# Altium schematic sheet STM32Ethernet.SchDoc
size A2
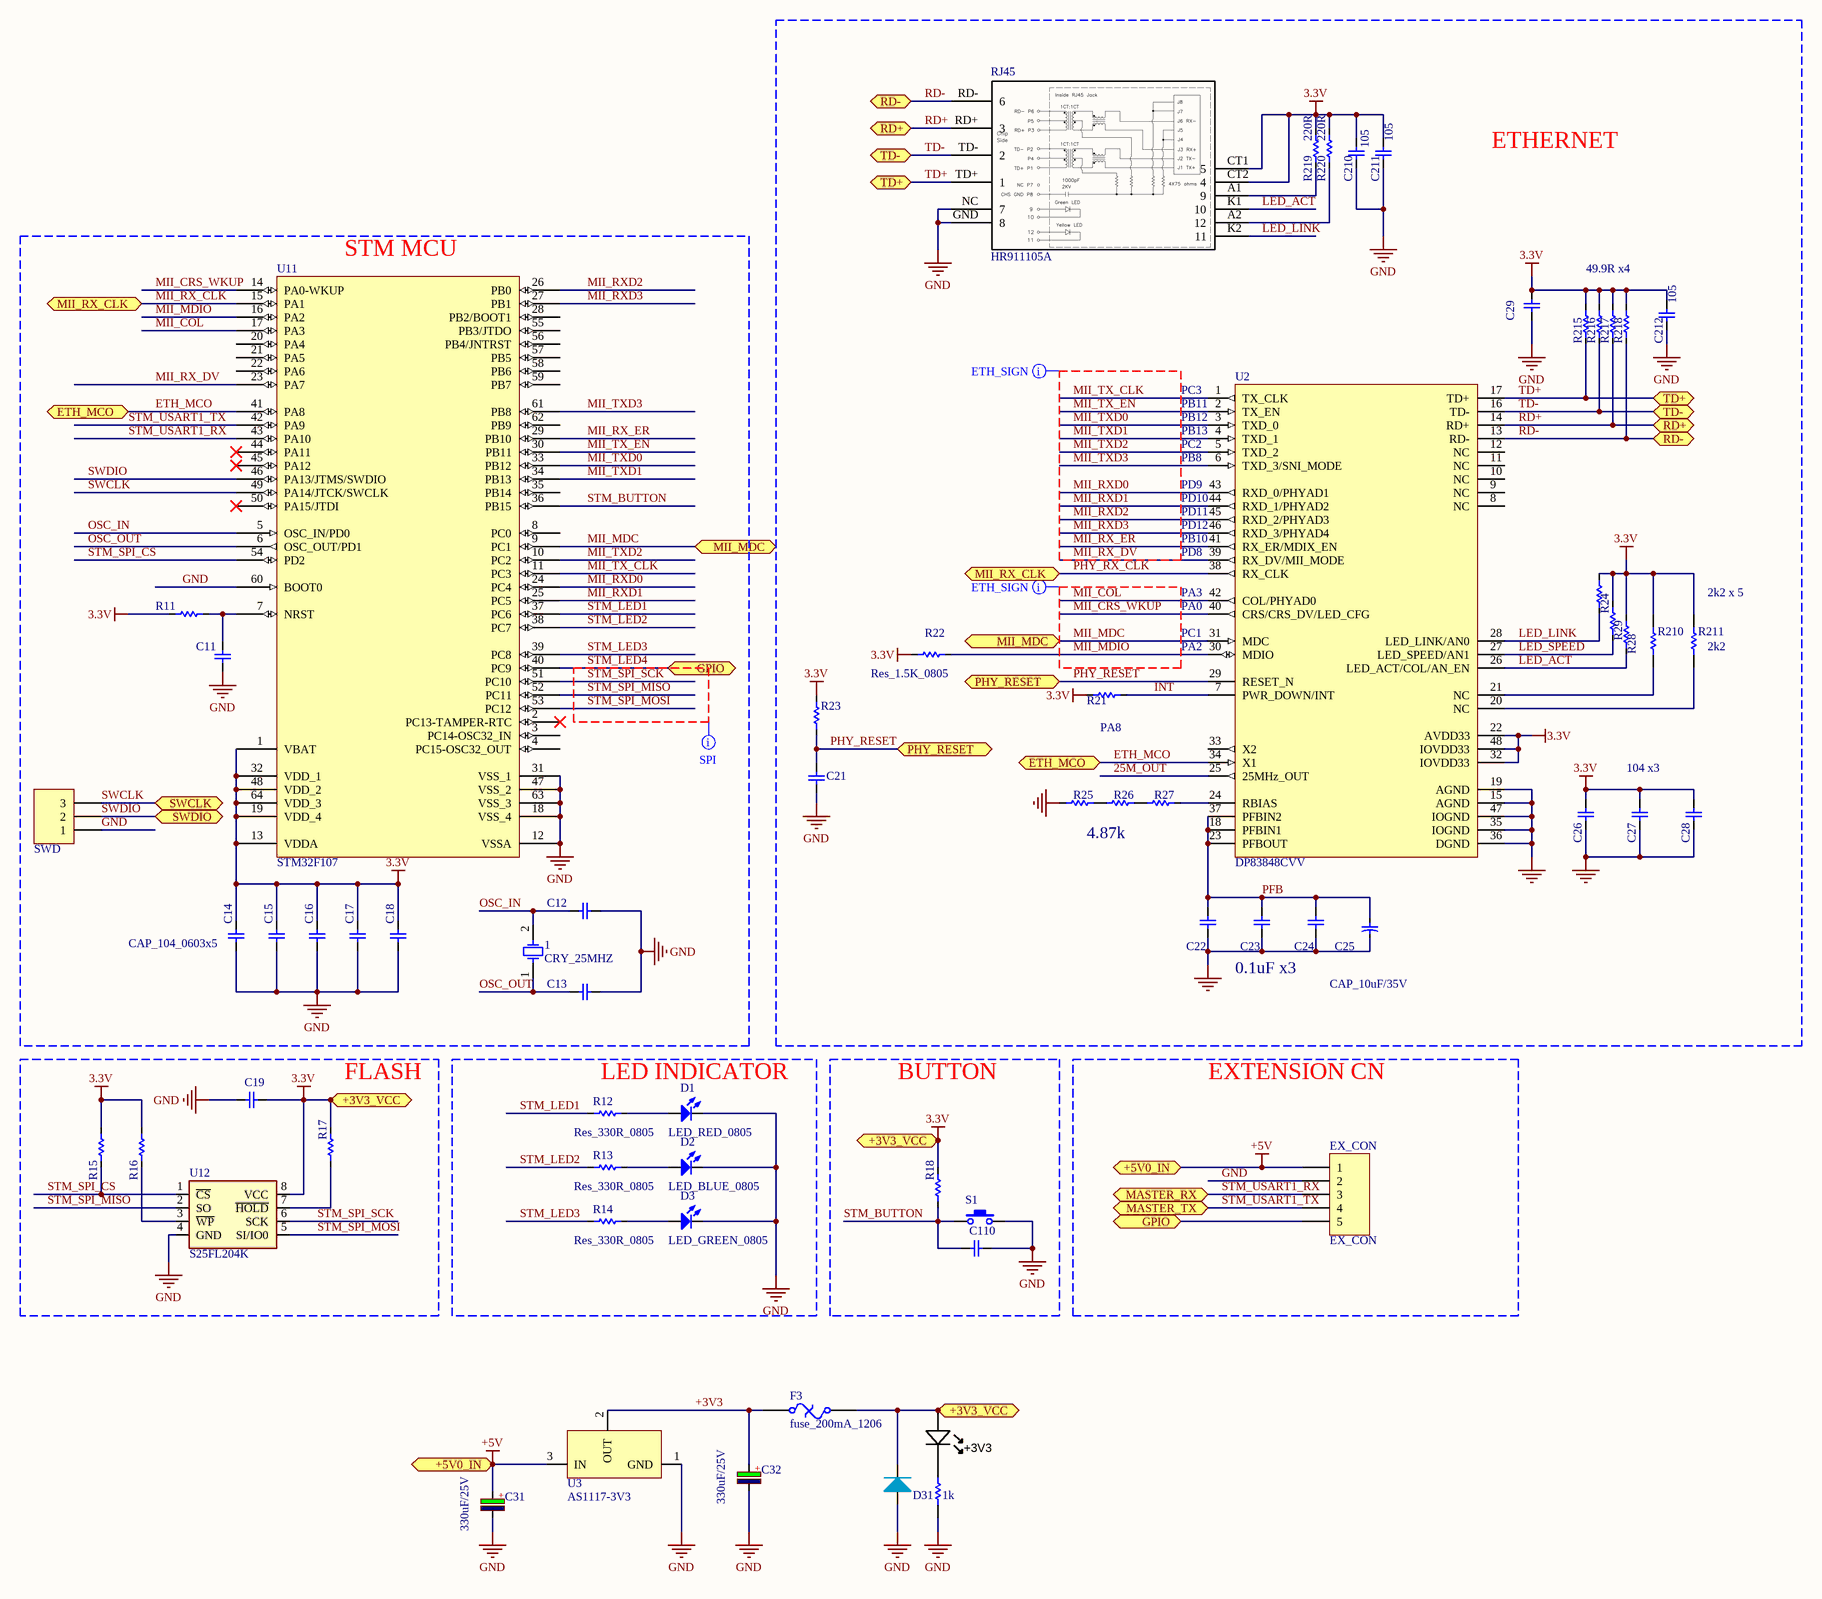
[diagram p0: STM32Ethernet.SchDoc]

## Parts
1  CRY_25MHZ  [cry]
+3V3  Blue  [LED-0805-K]  (value not drawn)
C11  CAP_102_0603  [CAP_0805_TOP]  (value not drawn)
C12  CAP_18pF_0603  [CAP_0603_TOP]  (value not drawn)
C13  CAP_18pF_0603  [CAP_0603_TOP]  (value not drawn)
C14  CAP_104_0603  [CAPC1608N_F]  (value not drawn)
C15  CAP_104_0603  [CAPC1608N_F]  (value not drawn)
C16  CAP_104_0603  [CAPC1608N_F]  (value not drawn)
C17  CAP_104_0603  [CAPC1608N_F]  (value not drawn)
C18  CAP_104_0603  [CAPC1608N_F]  (value not drawn)
C19  CAP_104_0603  [CAP_0805_TOP]  (value not drawn)
C21  CAP_102_0603  [CAPC1608N_F]  (value not drawn)
C22  CAP_104_0603  [CAPC1608N_F]  (value not drawn)
C23  CAP_104_0603  [CAPC1608N_F]  (value not drawn)
C24  CAP_104_0603  [CAPC1608N_F]  (value not drawn)
C25  CAP_10uF/35V  [CAP_10uF/35V]
C26  CAP_104_0603  [CAPC1608N_F]  (value not drawn)
C27  CAP_104_0603  [CAPC1608N_F]  (value not drawn)
C28  CAP_104_0603  [CAPC1608N_F]  (value not drawn)
C29  CAP_104_0603  [CAPC2012N_F]  (value not drawn)
C31  330uF/25V  [CAPMP3528X210N]
C32  330uF/25V  [CAPMP3528X210N]
C110  CAP_102_0603  [CAP_0805_TOP]  (value not drawn)
C210  105  [CAPC1608N_F]
C211  105  [CAPC1608N_F]
C212  105  [CAPC2012N_F]
D1  LED_RED_0805  [LED 0805 TOP]
D2  LED_BLUE_0805  [LED 0805 TOP]
D3  LED_GREEN_0805  [LED 0805 TOP]
D31  Diode  [DO-214AC]  (value not drawn)
EX_CON  EX_CON  [HDR1X5]
F3  fuse_200mA_1206  [SMD 1206]
R11  Res_4.7K_0805  [RES_0805_TOP]  (value not drawn)
R12  Res_330R_0805  [RES_0805_TOP]
R13  Res_330R_0805  [RES_0805_TOP]
R14  Res_330R_0805  [RES_0805_TOP]
R15  Res_4.7K_0805  [RES_0805_TOP]  (value not drawn)
R16  Res_4.7K_0805  [RES_0805_TOP]  (value not drawn)
R17  Res_4.7K_0805  [RES_0805_TOP]  (value not drawn)
R18  Res_4.7K_0805  [RES_0805_TOP]  (value not drawn)
R21  Res_2.2K_0805  [RESC1608N_F]  (value not drawn)
R22  Res_1.5K_0805  [RESC1608N_F]
R23  Res_4.7K_0805  [RESC1608N_F]  (value not drawn)
R24  Res_2.2K_0805  [RESC1608N_F]  (value not drawn)
R25  Res_47R_0805  [RES_0805_TOP]  (value not drawn)
R26  Res_120R_0805  [RES_0805_TOP]  (value not drawn)
R27  Res_4.7K_0805  [RES_0805_TOP]  (value not drawn)
R28  Res_0R_0603  [RESC1608N_F]  (value not drawn)
R29  Res_0R_0603  [RESC1608N_F]  (value not drawn)
R210  2k2  [RESC1608N_F]  (value not drawn)
R211  2k2  [RESC1608N_F]
R215  Res_49.9R_0805  [RES_0805_TOP]  (value not drawn)
R216  Res_49.9R_0805  [RES_0805_TOP]  (value not drawn)
R217  Res_49.9R_0805  [RES_0805_TOP]  (value not drawn)
R218  Res_49.9R_0805  [RES_0805_TOP]  (value not drawn)
R219  220R  [RESC1608N_F]
R220  220R  [RESC1608N_F]
RJ45  HR911105A  [HR911105A]
Rled  value 1k  [RESC2012N_F]  (hidden comment: Res_0805_1k)
S1  BUTTON 2P  [Nut nhan 2 chan  dung]  (value not drawn)
SWD  Header 3  [HDR1X3]  (value not drawn)
U2  DP83848CVV  [LQFP48]
U3  AS1117-3V3  [SOT223-4N]
U11  STM32F107  [LQFP64_N]
U12  S25FL204K  [SOIC_8]

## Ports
+3V3_VCC, +5V0_IN, ETH_MCO, GPIO, MASTER_RX, MASTER_TX, MII_MDC, MII_RX_CLK, PHY_RESET, RD+, RD-, SWCLK, SWDIO, TD+, TD-

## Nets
3.3V: +3V3.A C14.1 C15.1 C16.1 C17.1 C18.1 C19.1 C26.2 C27.1 C28.2 C29.1 C210.1 C211.1 C212.1 D31.2(K) F3.2 R11.2 R15.1 R16.1 R17.1 R18.1 R21.2 R22.1 R23.2 R24.2 R28.1 R29.2 R210.2 R211.2 R215.1 R216.1 R217.1 R218.1 R219.1 R220.1 RJ45.CT1(5) RJ45.CT2(4) U2.22(AVDD33) U2.32(IOVDD33) U2.48(IOVDD33) U11.1(VBAT) U11.13(VDDA) U11.19(VDD_4) U11.32(VDD_1) U11.48(VDD_2) U11.64(VDD_3) U12.8(VCC) ; port +3V3_VCC
+5V: C31.1 EX_CON.1 U3.3(IN) ; port +5V0_IN
GND: C11.2 C12.2 C13.2 C14.2 C15.2 C16.2 C17.2 C18.2 C19.2 C21.1 C22.1 C23.1 C24.1 C25.2 C26.1 C27.2 C28.1 C29.2 C31.2 C32.2 C110.2 C210.2 C211.2 C212.2 D1.2(K) D2.2(K) D3.2(K) D31.1(A) EX_CON.2 R25.2 RJ45.GND(8) RJ45.NC(7) Rled.2 S1.2 SWD.1 U2.15(AGND) U2.19(AGND) U2.35(IOGND) U2.36(DGND) U2.47(IOGND) U3.1(GND) U11.12(VSSA) U11.18(VSS_4) U11.31(VSS_1) U11.47(VSS_2) U11.60(BOOT0) U11.63(VSS_3) U12.4(GND)
25M_OUT: U2.25(25MHz_OUT)
+3V3: C32.1 F3.1 U3.2(OUT)
ETH_MCO: U2.34(X1) U11.41(PA8) ; port ETH_MCO
INT: R21.1 U2.7(PWR_DOWN/INT)
LED_ACT: R28.2 RJ45.K1(10) U2.26(LED_ACT/COL/AN_EN)
LED_LINK: R24.1 RJ45.K2(11) U2.28(LED_LINK/AN0)
LED_SPEED: R29.1 U2.27(LED_SPEED/AN1)
MII_COL: U2.42(COL/PHYAD0) U11.17(PA3)
MII_CRS_WKUP: U2.40(CRS/CRS_DV/LED_CFG) U11.14(PA0-WKUP)
MII_MDC: U2.31(MDC) U11.9(PC1) ; port MII_MDC
MII_MDIO: R22.2 U2.30(MDIO) U11.16(PA2)
MII_RX_CLK: U2.38(RX_CLK) U11.15(PA1) ; port MII_RX_CLK  [also labelled PHY_RX_CLK]
MII_RX_DV: U2.39(RX_DV/MII_MODE) U11.23(PA7)
MII_RX_ER: U2.41(RX_ER/MDIX_EN) U11.29(PB10)
MII_RXD0: U2.43(RXD_0/PHYAD1) U11.24(PC4)
MII_RXD1: U2.44(RXD_1/PHYAD2) U11.25(PC5)
MII_RXD2: U2.45(RXD_2/PHYAD3) U11.26(PB0)
MII_RXD3: U2.46(RXD_3/PHYAD4) U11.27(PB1)
MII_TX_CLK: U2.1(TX_CLK) U11.11(PC3)
MII_TX_EN: U2.2(TX_EN) U11.30(PB11)
MII_TXD0: U2.3(TXD_0) U11.33(PB12)
MII_TXD1: U2.4(TXD_1) U11.34(PB13)
MII_TXD2: U2.5(TXD_2) U11.10(PC2)
MII_TXD3: U2.6(TXD_3/SNI_MODE) U11.61(PB8)
OSC_IN: 1.2(OSC2) C12.1 U11.5(OSC_IN/PD0)
OSC_OUT: 1.1(OSC1) C13.1 U11.6(OSC_OUT/PD1)
PFB: C22.2 C23.2 C24.2 C25.1 U2.18(PFBIN1) U2.23(PFBOUT) U2.37(PFBIN2)
PHY_RESET: C21.2 R23.1 U2.29(RESET_N) ; port PHY_RESET
RD+: R217.2 RJ45.RD+(3) U2.14(RD+) ; port RD+
RD-: R218.2 RJ45.RD-(6) U2.13(RD-) ; port RD-
STM_BUTTON: C110.1 R18.2 S1.1 U11.36(PB15)
STM_LED1: R12.1 U11.37(PC6)
STM_LED2: R13.1 U11.38(PC7)
STM_LED3: R14.1 U11.39(PC8)
STM_LED4: EX_CON.5 U11.40(PC9) ; port GPIO
STM_SPI_CS: R15.2 U11.54(PD2) U12.1(~{CS})
STM_SPI_MISO: U11.52(PC11) U12.2(SO)
STM_SPI_MOSI: U11.53(PC12) U12.5(SI/IO0)
STM_SPI_SCK: U11.51(PC10) U12.6(SCK)
STM_USART1_RX: EX_CON.3 U11.43(PA10) ; port MASTER_RX
STM_USART1_TX: EX_CON.4 U11.42(PA9) ; port MASTER_TX
SWCLK: SWD.3 U11.49(PA14/JTCK/SWCLK) ; port SWCLK
SWDIO: SWD.2 U11.46(PA13/JTMS/SWDIO) ; port SWDIO
TD+: R215.2 RJ45.TD+(1) U2.17(TD+) ; port TD+
TD-: R216.2 RJ45.TD-(2) U2.16(TD-) ; port TD-
Net+3V3_K: +3V3.K Rled.1
NetC11_1: C11.1 R11.1 U11.7(NRST)
NetD1_1: D1.1(A) R12.2
NetD2_1: D2.1(A) R13.2
NetD3_1: D3.1(A) R14.2
NetR16_2: R16.2 U12.3(~{WP})
NetR17_2: R17.2 U12.7(~{HOLD})
NetR25_1: R25.1 R26.1
NetR26_2: R26.2 R27.2
NetR27_1: R27.1 U2.24(RBIAS)
NetR210_1: R210.1 U2.21(NC)
NetR211_1: R211.1 U2.20(NC)
NetR219_2: R219.2 RJ45.A1(9)
NetR220_2: R220.2 RJ45.A2(12)

Not connected (* = marked no-connect by the designer): U2 8(NC) 9(NC) 10(NC) 11(NC) 12(NC) 33(X2); U11 2(PC13-TAMPER-RTC)* 3(PC14-OSC32_IN) 4(PC15-OSC32_OUT) 8(PC0) 20(PA4) 21(PA5) 22(PA6) 28(PB2/BOOT1) 35(PB14) 44(PA11)* 45(PA12)* 50(PA15/JTDI)* 55(PB3/JTDO) 56(PB4/JNTRST) 57(PB5) 58(PB6) 59(PB7) 62(PB9)

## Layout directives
net class ETH_SIGN: 3.3V, 25M_OUT, ETH_MCO, GND, INT, LED_ACT, LED_LINK, LED_SPEED, MII_COL, MII_CRS_WKUP, MII_MDC, MII_MDIO, MII_RX_DV, MII_RX_ER, MII_RXD0, MII_RXD1, MII_RXD2, MII_RXD3, MII_TX_CLK, MII_TX_EN, MII_TXD0, MII_TXD1, MII_TXD2, MII_TXD3, PFB, PHY_RESET, PHY_RX_CLK, RD+, RD-, TD+, TD-
net class SPI_DATA: 3.3V, ETH_MCO, GND, MII_COL, MII_CRS_WKUP, MII_MDC, MII_MDIO, MII_RX_CLK, MII_RX_DV, MII_RX_ER, MII_RXD0, MII_RXD1, MII_RXD2, MII_RXD3, MII_TX_CLK, MII_TX_EN, MII_TXD0, MII_TXD1, MII_TXD2, MII_TXD3, OSC_IN, OSC_OUT, STM_BUTTON, STM_LED1, STM_LED2, STM_LED3, STM_LED4, STM_SPI_CS, STM_SPI_MISO, STM_SPI_MOSI, STM_SPI_SCK, STM_USART1_RX, STM_USART1_TX, SWCLK, SWDIO

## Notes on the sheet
- ETHERNET
- (near U11) STM MCU
- 49.9R x4
- (near U2) PC3
- (near U2) PB11
- (near U2) PB12
- (near U2) PB13
- (near U2) PC2
- (near U2) PB8
- (near U2) PD9
- (near U2) PD10
- (near U2) PD11
- (near U2) PD12
- (near U2) PB10
- (near U2) PD8
- (near U2) PA3
- (near U2) PA0
- (near R211) 2k2 x 5
- (near U2) PC1
- (near U2) PA2
- (near R21) PA8
- 104 x3
- 4.87k
- (near C14) CAP_104_0603x5
- 0.1uF x3
- (near R17) FLASH
- LED INDICATOR
- BUTTON
- EXTENSION CN

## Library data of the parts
1 = cry: Crystal Oscillator
+3V3 = LED_SMD_Blue_0805_100mcd: LED 0805 SMD Blue 100mcd 470nm; Manufacturer 1: Ligitek; Manufacturer Part Number 1: LG-170DBKZ-CT; Ratings: 100 mcd; 470 nm
C11-C19 C21-C24 C26-C29 C110 C210-C212 = Cap 1206 BUT: Capacitor; Value: 104
C25 = CAP P: Value: CAP_220uF/6.3V
C31 C32 = CP4: Cap 1000uF/16V - 220uF/50V; Description 5: 4,7uF>10uF/250V_3,3uF>10uF/400V - 2,2uF>4,7uF/450V; Description 1: 2200uF-3300uF/6,3V - 1000uF-2200uF/10V; Description 2: 1000uF/16V - 470uF => 1000uF/25V - 100uF/100V; Description 3: 330uF>470uF/35V_220uF>470uF/50V_10uF>22uF/250V; Description 4: 220uF => 330uF/63V - 10uF =>33uF/160 - 200V
D1-D3 = LED 0805 TOP: Typical INFRARED GaAs LED
D31 = Diode: pin to pad: 1>A 2>K
EX_CON = Header 5: Header, 5-Pin
F3 = Fuse Thermal: Thermal Fuse
R11-R18 R21-R29 R215-R220 = Res: Resistor
R210 R211 = Res: Value: 10k
RJ45 = RJ45-LED: pin to pad: A1>12 A2>9 CT1>4 CT2>5 GND>8 K1>11 K2>10 NC>7 RD+>3 RD->6 TD+>1 TD->2
Rled = Res
S1 = BUTTON 2P: Switch
SWD = Header 3: Header, 3-Pin
U3 = AS1117: pin to pad: 2>2+4
U11 = STM32F103RBT6: STM32 ARM-based 32-bit MCU with 128 Kbytes Flash, 64-pin LQFP, Industrial Temperature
